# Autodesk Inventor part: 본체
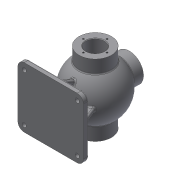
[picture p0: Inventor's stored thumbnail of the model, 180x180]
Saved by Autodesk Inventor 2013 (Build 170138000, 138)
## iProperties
Created: 2018-06
Part Number: 본체
Material: 일반
Document SubType Name: Modeling
Designer: Administrator
Density: 1 g/cm^3
Author: Administrator
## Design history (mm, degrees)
sketch "스케치2"
  geometry: L1 (0, 103.075)-(0, -103.075); A1 r 53 centre (0, 0) between (0, -53) and (0, 53); 2 further points
  constraints: 2 coincident, 2 end point, 2 point on circle, 2 point on line, 1 centre point, 1 midpoint, 1 vertical
  dimensions: "d0" = 106 diameter of A1
revolve "회전1" sketch "스케치2" stored, may be unused: angle "d1" = 90 deg
node "작업 평면1"
sketch "스케치4"
  geometry: C1 r 31 at (0, 0); 1 further point
  constraints: 1 centre point, 1 coincident
  dimensions: "d3" = 62 diameter of C1
extrude "돌출1" join sketch "스케치4" distance "d4" = 136; taper "d5" = 0 deg
sketch "스케치5"
  geometry: L1 (0, -49.435)-(0, 49.435); A1 r 43 centre (0, 0) between (0, -43) and (0, 43); 2 further points
  constraints: 2 coincident, 2 end point, 2 point on circle, 2 point on line, 1 centre point, 1 midpoint, 1 vertical
  dimensions: "d6" = 86 diameter of A1
revolve "회전2" sketch "스케치5" stored, may be unused: angle "d7" = 90 deg
sketch "스케치6"
  geometry: C1 r 31 at (0, 0) reference; C2 r 17.5 at (0, 0)
  constraints: 1 centre point, 1 coincident
  dimensions: "d8" = 35 diameter of C2
extrude "돌출2" cut sketch "스케치6" stored distance "d9" = 136; taper "d10" = 0 deg
node "작업 평면2"
sketch "스케치7"
  geometry: L1 (62.5, -57.5)-(-62.5, -57.5); L2 (-62.5, -57.5)-(-62.5, 57.5); L3 (-62.5, 57.5)-(62.5, 57.5); L4 (62.5, 57.5)-(62.5, -57.5); L5 (62.5, -57.5)-(-62.5, 57.5); L6 (-62.5, -57.5)-(62.5, 57.5); 1 further point
  constraints: 12 end point, 2 midpoint, 2 parallel, 1 horizontal, 1 perpendicular
  dimensions: "d12" = 125 distance of L2.end L3.end; "d13" = 115 distance of L1.end L2.end
extrude "돌출3" join sketch "스케치7" distance "d14" = 10; taper "d15" = 0 deg
fillet "모깎기1" dims "d16" = 12
sketch "스케치8"
  geometry: L1 (-31.053, 29.744)-(-75, 47.5); L2 (-75, 47.5)-(-75, -47.5); L3 (-75, -47.5)-(-31.053, -29.744); L4 (-75, -57.5)-(-85, -57.5) reference; L5 (-85, 57.5)-(-75, 57.5) reference; L6 (-75, -45.5)-(-75, 45.5) reference; A1 r 43 centre (0, 0) between (-31.053, 29.744) and (-31.053, -29.744); 2 further points
  constraints: 6 end point, 2 midpoint, 2 point on circle, 1 centre point, 1 coincident, 1 vertical
  dimensions: "d18" = 86 diameter of A1; "d20" = 10 distance from line of L4 L2.end; "d21" = 10 distance from line of L5 L1.end; "d22" = 22 deg angle of L5 L1; "d23" = 22 deg angle of L4 L3
extrude "돌출4" join sketch "스케치8" stored distance "d24" = 8; taper "d25" = 0 deg
sketch "스케치9"
  geometry: L1 (-52.5, -75)-(-42.423, -50.06); L2 (-62.5, -75)-(-62.5, -85) reference; L3 (-50.5, -75)-(50.5, -75) reference; 1 further point
  constraints: 2 end point, 1 point on line
  dimensions: "d26" = 10 distance from line of L2 L1.start; "d27" = 22 deg angle of L2 L1
feature "리브1" sketch "스케치9" dims "d28" = 1, "d29" = 8, "d30" = 0, "d31" = 0, "d32" = 1, "d33" = 1
node "작업 평면3"
sketch "스케치11"
  geometry: C1 r 27 at (0, 0); 1 further point
  constraints: 1 centre point, 1 coincident
  dimensions: "d44" = 54 diameter of C1
extrude "돌출5" join sketch "스케치11" stored distance "d45" = 8; taper "d46" = 0 deg
sketch "스케치12"
  geometry: C1 r 27 at (0, 0) reference; C2 r 13 at (0, 0)
  constraints: 1 centre point, 1 coincident
  dimensions: "d47" = 26 diameter of C2
extrude "돌출6" cut sketch "스케치12" stored distance "d48" = 8; taper "d49" = 0 deg
sketch "스케치13"
  geometry: L1 (18.5, -50.25)-(0, -50.25); L2 (0, -50.25)-(0, -52); L3 (0, -52)-(18.5, -52); L4 (18.5, -52)-(18.5, -50.25); L5 (17.5, -68)-(-17.5, -68) reference; 2 further points
  constraints: 8 end point, 2 parallel, 1 horizontal, 1 midpoint, 1 perpendicular, 1 vertical alignment
  dimensions: "d50" = 1.75 distance of L1.end L2.end; "d52" = 16 distance between parallel lines of L5 L3; "d54" = 37 diameter of L4 L2
revolve "회전3" sketch "스케치13" stored, may be unused: angle "d55" = 90 deg
sketch "스케치14"
  geometry: C1 r 17.5 at (0, 0) reference; 1 further point
  constraints: 1 vertical alignment
  dimensions: "d56" = 22.5 distance of C1.centre point (0, 22.5)
hole "구멍2" sketch "스케치14" at (0, 22.5) diameter "d57" = 3.242; stored, may be unused: countersink angle "d61" = 90 deg, drill point angle "d63" = 118 deg; dims "d58" = 12, "d59" = 12, "d60" = 3, "d62" = 15
sketch "스케치15"
  geometry: C1 r 17.5 at (0, 0) reference; 1 further point
  constraints: 1 vertical alignment
  dimensions: "d67" = 24 distance of C1.centre point (0, 24)
hole "구멍3" sketch "스케치15" at (0, 24) diameter "d68" = 3.242; stored, may be unused: countersink angle "d72" = 90 deg, drill point angle "d74" = 118 deg; dims "d69" = 16, "d70" = 12, "d71" = 3, "d73" = 19
sketch "스케치16"
  geometry: C1 r 13 at (0, 0) reference; 1 further point
  constraints: 1 vertical alignment
  dimensions: "d78" = 20 distance of C1.centre point (0, 20)
hole "구멍4" sketch "스케치16" at (0, 20) diameter "d79" = 3.242; stored, may be unused: countersink angle "d83" = 90 deg, drill point angle "d85" = 118 deg; dims "d80" = 9, "d81" = 12, "d82" = 3, "d84" = 11
node "작업 평면4"
sketch "스케치18"
  geometry: 2 further points
  dimensions: "d94" = 50.5 horizontal distance of point (-50.5, 45.5) point (0, 0); "d95" = 45.5 vertical distance of point (0, 0) point (-50.5, 45.5)
hole "구멍5" sketch "스케치18" at (-50.5, 45.5) diameter "d96" = 8; stored, may be unused: countersink angle "d100" = 90 deg, drill point angle "d102" = 118 deg; dims "d97" = 9, "d98" = 12, "d99" = 3, "d101" = 11
chamfer "모따기1" distance "d103" = 1; stored, may be unused: second distance "d104" = 2, angle "d105" = 45 deg
fillet "모깎기3" dims "d107" = 3, "d108" = 3
fillet "모깎기4" dims "d109" = 3
node "작업 평면5"
sketch "스케치20"
  geometry: L1 (-65, -27)-(-47.286, -27) reference; L2 (-65, -27)-(-65, 27) reference; 2 further points
  constraints: 1 other
  dimensions: "d111" = 27 distance from line of L1 point (-55, 0); "d112" = 10 distance from line of L2 point (-55, 0)
feature "엠보싱2" sketch "스케치20" dims "d113" = 0.5, "d114" = 0
node "솔리드1"
mirror "대칭1"
pattern_circular "원형 패턴1" dims angle "d65" = 360 deg
pattern_circular "원형 패턴2" dims angle "d76" = 360 deg
pattern_circular "원형 패턴3" dims angle "d87" = 360 deg
mirror "대칭4"
mirror "대칭5"
other parameters: "d2" = 68, "d11" = -85, "d89" = 27.5, "d110" = -27.5
